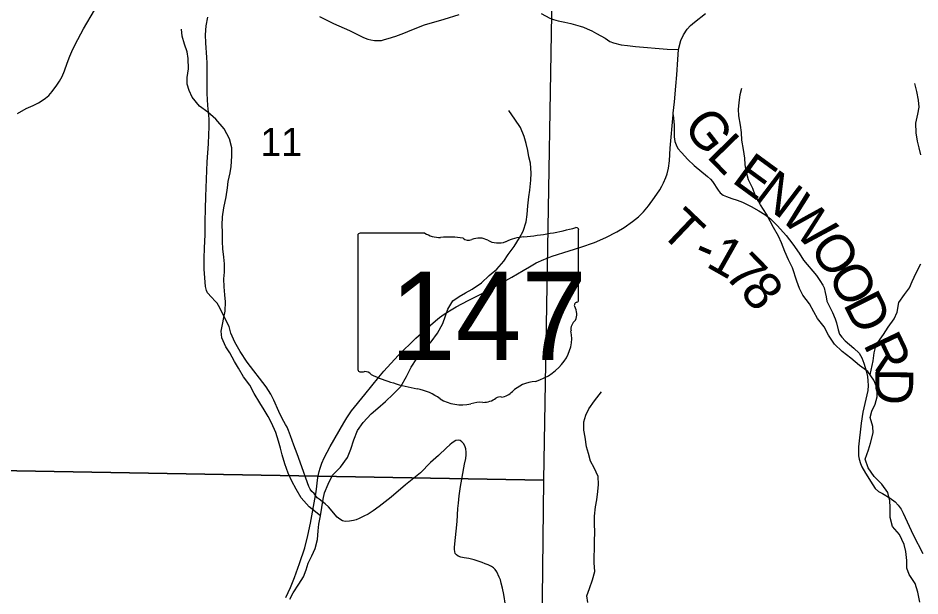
# Model space of a CAD drawing. Extents: x 0 to 34, y 0 to 22.
# Drawn here: x 25.254 to 26.601, y 18.434 to 19.296 of the extents above; entities that cross this region are included whole.
import ezdxf

# ---------------------------------------------------------------- set-up
doc = ezdxf.new("R2010")
doc.units = 0
for name, color, linetype in [('GM_X_Corporation', 7, 'Continuous'), ('GM_X_County_Road', 7, 'Continuous'), ('GM_X_Minor_River', 7, 'Continuous'), ('GM_X_Section_Text', 7, 'Continuous'), ('GM_X_State_Location', 7, 'Continuous'), ('GM_X_State_Route', 7, 'Continuous'), ('GM_X_State_Shield', 7, 'Continuous'), ('GM_X_Township_Road', 7, 'Continuous'), ('GM_X_Township_Road_Text', 7, 'Continuous')]:
    doc.layers.add(name, color=color, linetype=linetype)

msp = doc.modelspace()

# ---------------------------------------------------------------- linework, layer by layer
at = {"layer": 'GM_X_Corporation'}
for points in [[(25.037, 19.6422), (26.0559, 19.6207), (26.0385, 18.6067), (25.0268, 18.6245)], [(25.0268, 18.6245), (26.0385, 18.6067), (26.0272, 17.5944), (25.0136, 17.617)]]:
    msp.add_lwpolyline(points, close=True, dxfattribs=at)
at = {"layer": 'GM_X_County_Road'}
for points in [[(25.7043, 19.2986), (25.7252, 19.2882), (25.7487, 19.2775), (25.7696, 19.2672), (25.776, 19.2648), (25.7808, 19.2636), (25.7862, 19.2626), (25.7909, 19.2625), (25.7964, 19.2628), (25.8013, 19.264), (25.8067, 19.2655), (25.8178, 19.269), (25.8298, 19.2735), (25.8418, 19.2785), (25.8609, 19.2862), (25.8903, 19.2945), (25.9127, 19.3013)], [(26.0351, 19.3027), (26.0478, 19.2961), (26.0533, 19.2938), (26.0602, 19.292), (26.0702, 19.2899), (26.0791, 19.2878), (26.0934, 19.284), (26.0983, 19.2824), (26.1036, 19.2802), (26.1109, 19.2769), (26.1175, 19.2731), (26.1305, 19.266), (26.1376, 19.2613), (26.1428, 19.2593), (26.1544, 19.2562), (26.1639, 19.255), (26.1761, 19.2537), (26.2231, 19.2499), (26.2401, 19.2492)]]:
    msp.add_lwpolyline(points, dxfattribs=at)
at = {"layer": 'GM_X_Minor_River'}
for points in [[(25.7053, 18.5534), (25.6886, 18.5669), (25.6765, 18.5805), (25.6692, 18.593), (25.6627, 18.6052), (25.6574, 18.6173), (25.6521, 18.631), (25.6482, 18.6443), (25.6459, 18.6545), (25.6429, 18.6648), (25.6387, 18.678), (25.6325, 18.6921), (25.6272, 18.7019), (25.6215, 18.7118), (25.615, 18.722), (25.6063, 18.7361), (25.5998, 18.7482), (25.5906, 18.7607), (25.583, 18.7736), (25.5773, 18.7835), (25.57, 18.7964), (25.564, 18.8058), (25.5582, 18.8191), (25.5574, 18.829), (25.5593, 18.8389), (25.5612, 18.8495), (25.5631, 18.859), (25.5638, 18.8727), (25.5626, 18.883), (25.5618, 18.8951), (25.561, 18.9073), (25.5621, 18.9172), (25.5621, 18.9293), (25.5613, 18.9392), (25.5598, 18.9517), (25.5594, 18.9628), (25.5593, 18.9768), (25.5589, 18.9871), (25.5593, 18.9996), (25.5611, 19.0129), (25.5649, 19.0293), (25.5667, 19.0426), (25.5679, 19.0521), (25.5709, 19.065), (25.5724, 19.0745), (25.5731, 19.0901), (25.573, 19.1023), (25.5696, 19.1159), (25.5616, 19.1311), (25.5494, 19.1451), (25.5372, 19.1557), (25.5251, 19.1648), (25.514, 19.1781), (25.5094, 19.188), (25.5064, 19.1975), (25.5067, 19.2077), (25.5086, 19.2206), (25.5078, 19.2358), (25.5066, 19.2457), (25.5024, 19.2571), (25.499, 19.2689), (25.4978, 19.2795)], [(26.3305, 19.1695), (26.3323, 19.1821), (26.3348, 19.1916)], [(26.602, 19.0921), (26.5996, 19.1027), (26.5968, 19.1125), (26.5951, 19.125), (26.5946, 19.1391), (26.5974, 19.1528), (26.5995, 19.1634), (26.5983, 19.1736), (26.5958, 19.1865), (26.593, 19.1983)], [(26.6002, 18.4247), (26.5974, 18.4394), (26.5934, 18.4523), (26.5846, 18.4658), (26.581, 18.4756), (26.5809, 18.4866), (26.5796, 18.5003), (26.5768, 18.5109), (26.5698, 18.5256), (26.5595, 18.5376), (26.5559, 18.5508), (26.5561, 18.5664), (26.5556, 18.5758), (26.5528, 18.5883), (26.5435, 18.6007), (26.532, 18.612), (26.5235, 18.6251), (26.5189, 18.638), (26.5236, 18.6517), (26.5269, 18.662), (26.5308, 18.6772), (26.5303, 18.6867), (26.5264, 18.7003), (26.5285, 18.7098), (26.5337, 18.7201), (26.5366, 18.7311), (26.5368, 18.7437), (26.5317, 18.7561), (26.5229, 18.7689), (26.5103, 18.7779), (26.4973, 18.7887), (26.4843, 18.7988), (26.4728, 18.8096), (26.4639, 18.8232), (26.4577, 18.8356), (26.4477, 18.848), (26.4419, 18.8578), (26.4357, 18.8699), (26.4257, 18.8827), (26.4207, 18.8928), (26.4168, 18.9038), (26.4105, 18.9235), (26.4043, 18.9355), (26.3988, 18.9476), (26.3937, 18.9608), (26.3894, 18.9706), (26.3821, 18.9834), (26.377, 18.9932), (26.3716, 19.0034), (26.3624, 19.0177), (26.3546, 19.0317), (26.3511, 19.0419), (26.3445, 19.0547), (26.3409, 19.0676), (26.3397, 19.0774), (26.3392, 19.0869), (26.3371, 19.1001), (26.3347, 19.1138), (26.3341, 19.1252), (26.3325, 19.1361), (26.3304, 19.1502), (26.3295, 19.16), (26.3305, 19.1695)], [(25.7234, 18.6141), (25.7355, 18.6263), (25.7461, 18.6404), (25.7507, 18.6529), (25.7552, 18.667), (25.7608, 18.6807), (25.7695, 18.6929), (25.7813, 18.7055), (25.7911, 18.7142), (25.8025, 18.7241), (25.8142, 18.7348), (25.8256, 18.7463), (25.8339, 18.7615), (25.841, 18.7752), (25.8494, 18.7881), (25.8599, 18.8007), (25.8709, 18.8129), (25.88, 18.8262), (25.8883, 18.8403), (25.8921, 18.8517), (25.8958, 18.8616), (25.903, 18.8742), (25.9125, 18.8807), (25.922, 18.8864), (25.9322, 18.8917), (25.9458, 18.9009), (25.9576, 18.912), (25.9689, 18.9215), (25.9795, 18.9333), (25.9859, 18.9436), (25.9946, 18.9554), (26.0026, 18.9683), (26.0082, 18.9782), (26.0127, 18.9923), (26.0142, 19.003), (26.0153, 19.0159), (26.0168, 19.0296), (26.0179, 19.0395), (26.0198, 19.0543), (26.0201, 19.0649), (26.019, 19.0794), (26.0167, 19.0889), (26.0151, 19.0987), (26.0128, 19.109), (26.0097, 19.1192), (26.0044, 19.1329), (25.9956, 19.1454), (25.9865, 19.1583)], [(26.5263, 18.764), (26.5306, 18.7849), (26.5323, 18.7967), (26.5352, 18.8085), (26.546, 18.8238), (26.553, 18.8349), (26.5623, 18.8476), (26.5668, 18.8575), (26.5692, 18.8716), (26.5774, 18.8838), (26.5848, 18.8934), (26.5892, 18.9029), (26.5951, 18.9159), (26.6018, 18.9293)], [(26.1045, 18.4242), (26.1033, 18.4341), (26.1071, 18.4448), (26.1116, 18.4581), (26.115, 18.4702), (26.1142, 18.4832), (26.1142, 18.4926), (26.1146, 18.5037), (26.1149, 18.5151), (26.1152, 18.5295), (26.1148, 18.5409), (26.1148, 18.553), (26.1163, 18.5671), (26.1182, 18.5774), (26.1197, 18.5899), (26.1208, 18.6002), (26.12, 18.6119), (26.1143, 18.6252), (26.1089, 18.6351), (26.1055, 18.6465), (26.1028, 18.6563), (26.1005, 18.6708), (26.0989, 18.6814), (26.0985, 18.6939), (26.1015, 18.7034), (26.1064, 18.7133), (26.1148, 18.7251), (26.1253, 18.7385)], [(25.6598, 18.4289), (25.6647, 18.4384), (25.6734, 18.4514), (25.6802, 18.4624), (25.6839, 18.4727), (25.6873, 18.4826), (25.6926, 18.494), (25.6975, 18.5046), (25.7009, 18.5179), (25.702, 18.5312), (25.7031, 18.5411), (25.7054, 18.5536), (25.7076, 18.5658), (25.7095, 18.5784), (25.7114, 18.5879), (25.717, 18.6008), (25.7234, 18.6141)]]:
    msp.add_lwpolyline(points, dxfattribs=at)
at = {"layer": 'GM_X_State_Route'}
msp.add_lwpolyline([(25.6536, 18.4315), (25.6606, 18.4465), (25.6665, 18.4615), (25.6744, 18.4821), (25.6823, 18.5058), (25.6866, 18.5239), (25.6908, 18.5427), (25.698, 18.5838), (25.699, 18.5895), (25.7017, 18.6106), (25.7035, 18.6197), (25.705, 18.6245), (25.7073, 18.6318), (25.711, 18.6399), (25.7202, 18.6568), (25.7403, 18.6923), (25.7449, 18.6999), (25.752, 18.7101), (25.7716, 18.7347), (25.7925, 18.7602), (25.8001, 18.7692), (25.8215, 18.7927), (25.848, 18.8183), (25.856, 18.8256), (25.8662, 18.8351), (25.8772, 18.8444), (25.8833, 18.8494), (25.8901, 18.8545), (25.8982, 18.8595), (25.908, 18.8654), (25.9262, 18.8746), (25.9498, 18.8865), (25.9655, 18.8949), (25.9911, 18.9093), (26.0082, 18.9197), (26.0176, 18.9252), (26.0275, 18.9308), (26.0388, 18.936), (26.0516, 18.941), (26.077, 18.9487), (26.0941, 18.9541), (26.1146, 18.9612), (26.1318, 18.9687), (26.1482, 18.9772), (26.1589, 18.9834), (26.1716, 18.9925), (26.1802, 18.9994), (26.1879, 19.0069), (26.1954, 19.016), (26.204, 19.0283), (26.2121, 19.0399), (26.2153, 19.0451), (26.2179, 19.0505), (26.2213, 19.0584), (26.2231, 19.0639), (26.2251, 19.072), (26.2264, 19.083), (26.2275, 19.1021), (26.2319, 19.1516), (26.2322, 19.154), (26.2339, 19.1712), (26.2362, 19.1945), (26.2378, 19.2116), (26.2391, 19.2342), (26.2401, 19.2492), (26.2437, 19.2626), (26.2475, 19.2711), (26.2532, 19.2795), (26.2581, 19.285), (26.264, 19.2901), (26.2805, 19.3029)], dxfattribs=at)
at = {"layer": 'GM_X_State_Shield'}
for p, q in [((25.8612, 18.9752), (25.7647, 18.9752)), ((26.091, 18.8755), (26.091, 18.9802)), ((25.7615, 18.9718), (25.7615, 18.7717)), ((26.091, 18.8755), (26.091, 18.8755))]:
    msp.add_line(p, q, dxfattribs=at)
for centre, major_axis, start_param, end_param in [((25.7652, 18.9722), (0.00382, 0), 1.712693, 3.28349), ((25.8842, 18.9985), (0.037, 0), 4.042523, 4.731795), ((25.9736, 19.2481), (0.3495, 0), 4.814394, 5.042369), ((26.0874, 18.9806), (0.00367, 0), 6.141152, 7.989035), ((25.8965, 18.8629), (0.133, 0), 1.404758, 1.657858), ((25.9267, 18.9733), (0.0107, 0), 3.836095, 5.185415), ((25.9424, 18.9501), (0.0222, 0), 0.950623, 2.079405), ((25.971, 18.9819), (0.0267, 0), 4.081561, 5.145723), ((26.0182, 18.9141), (0.0703, 0), 1.699011, 2.107814), ((26.0902, 18.8678), (0.00568, 0), 1.883978, 3.671073), ((26.0871, 18.8751), (0.00393, 0), 5.05454, 6.418171), ((26.0541, 18.8546), (0.0341, 0), 5.934695, 6.695948), ((26.1042, 18.8317), (0.0248, 0), 2.387724, 3.262537), ((25.9932, 18.8184), (0.0874, 0), 5.101752, 6.440018), ((25.7653, 18.7712), (0.00385, 0), 3.00124, 4.508301), ((25.7659, 18.7917), (0.0294, 0), 4.665946, 4.897461), ((25.7719, 18.7601), (0.0106, 0), 0.519207, 1.627899), ((25.9057, 18.9399), (0.2524, 0), 4.195997, 4.488961), ((26.0301, 18.7155), (0.0479, 0), 1.647645, 2.488434), ((25.8304, 18.6818), (0.079, 0), 0.823519, 1.323587), ((25.9694, 18.7523), (0.0282, 0), 4.937069, 5.64225), ((25.9159, 18.7591), (0.0501, 0), 4.026481, 4.996735), ((25.9448, 18.6899), (0.0412, 0), 1.495662, 1.94098), ((25.9485, 18.7441), (0.0267, 0), 4.691044, 5.507374), ((25.9726, 18.7248), (0.00752, 0), 1.147584, 2.315152)]:
    msp.add_ellipse(centre, major_axis=major_axis, ratio=0.8, start_param=start_param, end_param=end_param, dxfattribs=at)
at = {"layer": 'GM_X_Township_Road'}
for points in [[(25.2531, 19.1539), (25.2663, 19.1613), (25.2764, 19.1656), (25.2846, 19.1696), (25.2902, 19.1729), (25.2947, 19.1764), (25.3, 19.1808), (25.3047, 19.1866), (25.3117, 19.1962), (25.3157, 19.202), (25.3197, 19.2089), (25.3235, 19.2176), (25.3273, 19.2289), (25.3311, 19.2392), (25.3342, 19.2464), (25.3392, 19.2565), (25.3518, 19.2803), (25.3683, 19.3081)], [(25.9817, 18.4202), (25.9794, 18.436), (25.9775, 18.4456), (25.9755, 18.4531), (25.9741, 18.4581), (25.9725, 18.4621), (25.9688, 18.4701), (25.9662, 18.4733), (25.9637, 18.4757), (25.9607, 18.4778), (25.9559, 18.4803), (25.9513, 18.4819), (25.9468, 18.4839), (25.9425, 18.4853), (25.9351, 18.4878), (25.9271, 18.4898), (25.9203, 18.4908), (25.9153, 18.492), (25.9111, 18.4935), (25.9085, 18.4952), (25.9068, 18.4974), (25.9059, 18.5003), (25.9057, 18.5031), (25.9055, 18.5067), (25.9094, 18.5452), (25.9108, 18.5646), (25.9114, 18.5722), (25.9125, 18.5833), (25.9144, 18.597), (25.9205, 18.6306), (25.9224, 18.6392), (25.923, 18.6445), (25.9231, 18.6484), (25.9224, 18.6535), (25.921, 18.6581), (25.9192, 18.6613), (25.9167, 18.6637), (25.9139, 18.6656), (25.9109, 18.6664), (25.9074, 18.6658), (25.9021, 18.6624), (25.8985, 18.6596), (25.8935, 18.6547), (25.8817, 18.6436), (25.8699, 18.6328), (25.8547, 18.6177), (25.8326, 18.5995), (25.8109, 18.5815), (25.7931, 18.5676), (25.7843, 18.5609), (25.7767, 18.5561), (25.7704, 18.5527), (25.7635, 18.5495), (25.7588, 18.5476), (25.7546, 18.5463), (25.7486, 18.5453), (25.7426, 18.5451), (25.7384, 18.5462), (25.7343, 18.5485), (25.7303, 18.5517), (25.7174, 18.5671), (25.7125, 18.5714), (25.7038, 18.5781), (25.7008, 18.5802), (25.698, 18.5838), (25.6971, 18.5852), (25.696, 18.5868), (25.6924, 18.5897), (25.6902, 18.593), (25.6881, 18.5974), (25.6861, 18.6025), (25.6775, 18.6264), (25.6706, 18.6459), (25.6657, 18.6591), (25.6609, 18.6729), (25.6579, 18.6808), (25.6556, 18.6855), (25.6533, 18.6896), (25.6483, 18.6988), (25.6433, 18.7092), (25.6358, 18.7261), (25.6316, 18.7349), (25.6245, 18.7459), (25.5963, 18.7825), (25.5858, 18.7985), (25.5774, 18.8125), (25.5717, 18.8258), (25.5692, 18.8358), (25.5633, 18.8474), (25.5589, 18.8568), (25.5533, 18.8671), (25.5512, 18.8706), (25.5484, 18.8739), (25.5426, 18.8795), (25.5367, 18.8864), (25.5352, 18.8898), (25.5338, 18.8954), (25.5317, 18.9217), (25.5317, 18.9377), (25.5324, 18.9526), (25.5332, 18.9731), (25.5333, 18.9927), (25.5336, 19.0115), (25.5343, 19.0297), (25.5365, 19.0815), (25.5385, 19.1084), (25.539, 19.1226), (25.5394, 19.1332), (25.5394, 19.1457), (25.5373, 19.1659), (25.5362, 19.1835), (25.5361, 19.2059), (25.5364, 19.2174), (25.5363, 19.2295), (25.536, 19.2371), (25.5344, 19.2591), (25.534, 19.2711), (25.535, 19.2845), (25.5374, 19.2974)], [(26.2319, 19.1516), (26.2335, 19.1364), (26.2337, 19.1282), (26.2337, 19.1189), (26.2345, 19.1121), (26.2364, 19.1068), (26.2393, 19.1014), (26.2447, 19.0954), (26.2541, 19.0851), (26.2635, 19.0764), (26.2835, 19.0595), (26.288, 19.0556), (26.291, 19.0522), (26.2994, 19.0394), (26.3024, 19.0356), (26.3066, 19.0321), (26.3116, 19.0297), (26.3196, 19.0268), (26.3279, 19.0243), (26.3354, 19.0212), (26.3484, 19.0148), (26.3601, 19.0086), (26.3688, 19.0031), (26.3772, 18.9965), (26.388, 18.9862), (26.4007, 18.9715), (26.411, 18.9589), (26.4202, 18.9453), (26.4269, 18.9351), (26.446, 18.9121), (26.4513, 18.9048), (26.4555, 18.8976), (26.4575, 18.8934), (26.4592, 18.8869), (26.4606, 18.8802), (26.4613, 18.8737), (26.4698, 18.8568), (26.4742, 18.8472), (26.4758, 18.8414), (26.4784, 18.8308), (26.4807, 18.8247), (26.484, 18.8201), (26.4891, 18.8144), (26.5018, 18.8036), (26.5097, 18.7961), (26.5136, 18.789), (26.517, 18.7813), (26.5203, 18.7696), (26.5222, 18.7614), (26.523, 18.755), (26.5232, 18.7479), (26.5226, 18.7404), (26.5155, 18.7082), (26.5127, 18.6918), (26.5089, 18.6566), (26.5086, 18.6485), (26.5088, 18.6429), (26.5096, 18.6379), (26.5118, 18.6316), (26.5138, 18.6267), (26.5194, 18.6173), (26.5303, 18.5995), (26.5339, 18.594), (26.5389, 18.5899), (26.5447, 18.5866), (26.556, 18.5797), (26.5635, 18.5743), (26.5682, 18.5692), (26.5723, 18.5633), (26.5754, 18.5576), (26.5905, 18.525), (26.6049, 18.497)]]:
    msp.add_lwpolyline(points, dxfattribs=at)

# ---------------------------------------------------------------- texts
at = {"layer": 'GM_X_Section_Text'}
msp.add_text('11', height=0.04186, rotation=0, dxfattribs=at).set_placement((25.6157, 19.0903))
at = {"layer": 'GM_X_State_Location'}
for s in ['s', 'r']:
    msp.add_text(s, height=0.000189, dxfattribs=at).set_placement((25.9225, 18.8584))
msp.add_text('147', height=0.000189, rotation=0, dxfattribs=at).set_placement((25.8557, 18.8446))
at = {"layer": 'GM_X_State_Shield'}
msp.add_text('147', height=0.13184, dxfattribs=at).set_placement((25.8093, 18.7858))
at = {"layer": 'GM_X_Township_Road_Text'}
for s, rotation, p in [('G', 307.6932, (26.2452, 19.1344)), ('L', 314.28, (26.2805, 19.0895)), ('E', 323.8527, (26.318, 19.0523)), ('N', 322.8161, (26.3521, 19.0274)), ('W', 313.3076, (26.3901, 18.9988)), ('T', 316.3759, (26.2104, 18.976)), ('1', 330.5152, (26.2794, 18.9262)), ('O', 305.4928, (26.4339, 18.9525)), ('-', 336.703, (26.2594, 18.9347)), ('7', 314.448, (26.3065, 18.9115)), ('O', 297.7854, (26.4619, 18.9135)), ('8', 309.5717, (26.3302, 18.8875)), ('D', 296.8502, (26.4851, 18.8695)), ('R', 295.4654, (26.5154, 18.8096)), ('D', 269.3224, (26.534, 18.7741))]:
    msp.add_text(s, height=0.0568, rotation=rotation, dxfattribs=at).set_placement(p)

doc.saveas('drawing.dxf')
